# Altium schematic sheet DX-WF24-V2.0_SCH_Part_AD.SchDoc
size A4
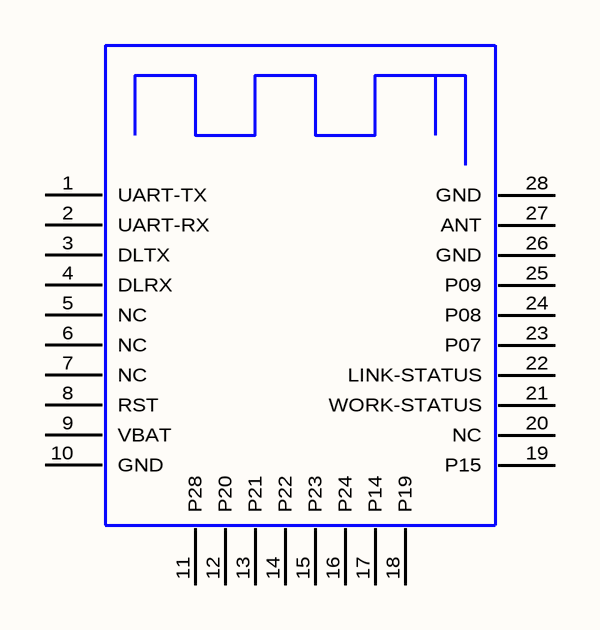
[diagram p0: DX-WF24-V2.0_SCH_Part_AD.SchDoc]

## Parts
U??  DX-WF24  [DX-WF24]  (value not drawn)

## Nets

Not connected (* = marked no-connect by the designer): U?? 1(UART-TX) 2(UART-RX) 3(DLTX) 4(DLRX) 5(NC) 6(NC) 7(NC) 8(RST) 9(VBAT) 10(GND) 11(P28) 12(P20) 13(P21) 14(P22) 15(P23) 16(P24) 17(P14) 18(P19) 19(P15) 20(NC) 21(WORK-STATUS) 22(LINK-STATUS) 23(P07) 24(P08) 25(P09) 26(GND) 27(ANT) 28(GND)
